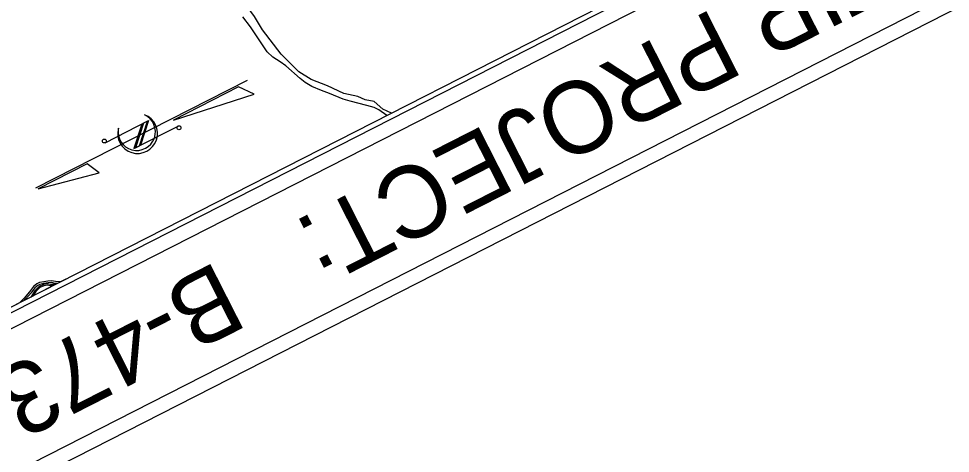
# Model space of a CAD drawing. Extents: x 558484 to 564063, y 513718 to 518374.
# Drawn here: x 559464.9 to 559790.1, y 514651.4 to 514802.9 of the extents above; entities that cross this region are included whole.
import ezdxf

# ---------------------------------------------------------------- set-up
doc = ezdxf.new("R2010")
doc.units = 0
for name, color, linetype in [('Default', 7, 'Continuous'), ('Scratch_Level_3', 7, 'Continuous'), ('Sheet North Arrow CELL', 7, 'Continuous'), ('Sheet Title CELL', 7, 'Continuous')]:
    doc.layers.add(name, color=color, linetype=linetype)

msp = doc.modelspace()

# ---------------------------------------------------------------- linework, layer by layer
at = {"layer": 'Default'}
msp.add_lwpolyline([(559363.74, 514652.18), (559165.18, 515042.19), (559493.11, 515209.15), (559691.68, 514819.14)], close=True, dxfattribs=at)
msp.add_lwpolyline([(559363.74, 514652.18), (559165.18, 515042.19), (559493.11, 515209.15), (559691.68, 514819.14)], close=True, dxfattribs=at)
for points in [[(559595.05, 514769.95), (559592.03, 514771.37), (559588.99, 514774), (559585.91, 514774.61), (559583.27, 514775.71), (559578.37, 514776.79), (559572.67, 514779.5), (559567.01, 514781.67), (559562.67, 514784.29), (559556.48, 514790.49), (559549.98, 514798.98), (559547.28, 514803.62), (559534.7, 514820.79), (559533.41, 514823.35), (559532.43, 514827.48), (559533.96, 514837.16), (559532.34, 514844.85), (559529.89, 514848.03), (559512.22, 514854.07), (559499.68, 514866.7), (559495.31, 514870.44), (559487.11, 514878.45), (559477.56, 514881.01), (559475.88, 514882.38)], [(559593.41, 514769.12), (559590.57, 514771.1), (559589.05, 514771.89), (559586.47, 514772.61), (559580.58, 514774.12), (559578.17, 514774.83), (559573.42, 514776.8), (559570.58, 514777.86), (559567.27, 514779.25), (559564.86, 514780.65), (559563.11, 514782.01), (559558.17, 514786.39), (559556.2, 514787.8), (559553.59, 514789.49), (559551.65, 514791.27), (559545.82, 514800.03), (559543.19, 514803.46)], [(559479.5, 514711.12), (559479.03, 514711.13), (559477.78, 514711.22), (559476.4, 514711.48), (559475.12, 514711.35), (559473.64, 514711.16), (559472.13, 514710.85), (559471.26, 514710.39), (559470.11, 514709.47), (559468.74, 514707.69), (559466.78, 514705.49), (559465.36, 514703.92)], [(559478.4, 514710.56), (559477.7, 514710.61), (559476.38, 514710.86), (559475.19, 514710.74), (559473.75, 514710.56), (559472.34, 514710.26), (559471.6, 514709.87), (559470.55, 514709.04), (559469.22, 514707.3), (559467.24, 514705.08), (559466.89, 514704.7)], [(559477.56, 514710.13), (559477.46, 514710.15), (559475.98, 514710.16), (559475, 514710.42), (559473.57, 514710.18), (559472.05, 514709.46), (559470.59, 514708.04), (559469.14, 514705.85)], [(559476.79, 514709.74), (559475.92, 514709.74), (559474.98, 514710), (559473.69, 514709.79), (559472.29, 514709.12), (559470.91, 514707.77), (559469.89, 514706.23)]]:
    msp.add_lwpolyline(points, dxfattribs=at)
at = {"layer": 'Scratch_Level_3'}
msp.add_line((559481.39, 514712.08), (559211.34, 514574.59), dxfattribs=at)
at = {"layer": 'Sheet North Arrow CELL'}
for p, q in [((559544.68, 514781.34), (559470.82, 514743.73)), ((559495.11, 514759.6), (559510.27, 514767.32)), ((559507.9, 514766.12), (559505.13, 514757.6)), ((559508.46, 514766.4), (559505.69, 514757.88)), ((559509.84, 514767.11), (559507.07, 514758.58)), ((559507.07, 514758.58), (559509.84, 514767.11)), ((559510.27, 514767.32), (559507.49, 514758.8)), ((559509.84, 514767.11), (559508.46, 514766.4)), ((559499.69, 514764.57), (559499.71, 514764.68)), ((559505.13, 514757.6), (559520.54, 514765.44)), ((559505.69, 514757.88), (559507.07, 514758.58))]:
    msp.add_line(p, q, dxfattribs=at)
for points in [[(559518.97, 514767.49), (559547.11, 514776.55), (559541.69, 514779.06)], [(559471.73, 514743.55), (559493.06, 514749.1), (559488.78, 514752.23)]]:
    msp.add_lwpolyline(points, close=True, dxfattribs=at)
for centre in [(559520.87, 514764.85), (559494.81, 514760.21)]:
    msp.add_circle(centre, 0.676, dxfattribs=at)
for centre, radius, start, end in [((559506.43, 514762.85), 6.96, 164.8219, 69.376), ((559506.12, 514763.45), 6.53, 170.077, 65.6106)]:
    msp.add_arc(centre, radius, start, end, dxfattribs=at)
at = {"layer": 'Sheet Title CELL'}
for p, q in [((560256.31, 515098.98), (559347.33, 514636.2)), ((560089.18, 515019.5), (559345.07, 514640.66))]:
    msp.add_line(p, q, dxfattribs=at)
for points in [[(559367.75, 514596.11), (560276.72, 515058.88)], [(559365.56, 514589.37), (560283.45, 515056.69)], [(559365.56, 514589.37), (560283.45, 515056.69)]]:
    msp.add_lwpolyline(points, dxfattribs=at)

# ---------------------------------------------------------------- texts
for s, p in [('TIP PROJECT:', (559762, 514834.54)), ('B-4734  ', (559534.25, 514718.59))]:
    msp.add_text(s, height=25, rotation=206.9819, dxfattribs=at).set_placement(p)

doc.saveas('drawing.dxf')
